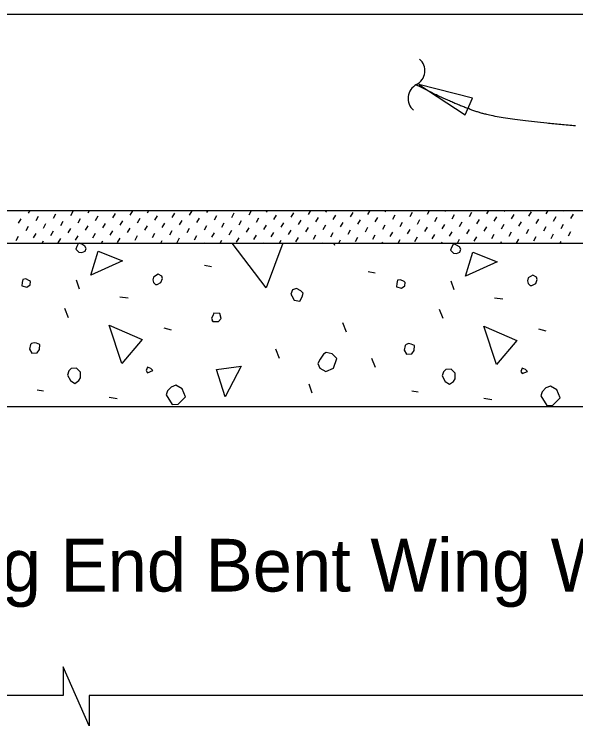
# Model space of a CAD drawing. Extents: x 2.6 to 35.7, y 1.7 to 23.4.
# Drawn here: x 9.781 to 11.926, y 5.942 to 8.663 of the extents above; entities that cross this region are included whole.
import ezdxf

# ---------------------------------------------------------------- set-up
doc = ezdxf.new("R2010")
doc.units = 0
for name, color, linetype in [('Dimension', 7, 'Continuous'), ('Miscellaneous', 7, 'Continuous'), ('TextStructures', 7, 'Continuous'), ('TrafBarrierConc', 7, 'Continuous')]:
    doc.layers.add(name, color=color, linetype=linetype)

msp = doc.modelspace()

# ---------------------------------------------------------------- linework, layer by layer
at = {"layer": 'Dimension'}
msp.add_lwpolyline([(11.327, 8.3948), (11.5032, 8.2783), (11.5318, 8.3428)], close=True, dxfattribs=at)
msp.add_lwpolyline([(12.6311, 6.0586), (10.0672, 6.0586), (10.0672, 5.9424), (9.9678, 6.1674), (9.9678, 6.0586), (8.3596, 6.0586)], dxfattribs=at)
for centre, start, end in [((11.2903, 8.4471), 297.3915, 49.1187), ((11.3452, 8.3413), 117.3915, 229.1187)]:
    msp.add_arc(centre, 0.0596, start, end, dxfattribs=at)
msp.add_open_spline([(11.9256, 8.2363), (11.6526, 8.2589), (11.4737, 8.3129), (11.3181, 8.3921)], degree=2, dxfattribs=at)
at = {"layer": 'Miscellaneous'}
for p, q in [((9.8355, 7.9025), (9.8418, 7.9134)), ((9.9018, 7.9122), (9.9025, 7.9134)), ((9.9301, 7.8839), (9.9398, 7.9007)), ((9.9964, 7.8937), (10.0061, 7.9105)), ((10.0627, 7.9034), (10.0685, 7.9134)), ((10.091, 7.8751), (10.1007, 7.8919)), ((10.129, 7.9131), (10.1291, 7.9134)), ((10.1573, 7.8848), (10.167, 7.9016)), ((10.2236, 7.8946), (10.2333, 7.9113)), ((10.2898, 7.9043), (10.2951, 7.9134)), ((10.3181, 7.876), (10.3279, 7.8928)), ((10.3844, 7.8857), (10.3941, 7.9025)), ((10.4507, 7.8954), (10.4604, 7.9122)), ((10.517, 7.9052), (10.5218, 7.9134)), ((10.5453, 7.8769), (10.555, 7.8937)), ((10.6116, 7.8866), (10.6213, 7.9034)), ((10.6779, 7.8963), (10.6876, 7.9131)), ((10.7442, 7.906), (10.7484, 7.9134)), ((10.7724, 7.8778), (10.7822, 7.8946)), ((10.8387, 7.8875), (10.8485, 7.9043)), ((10.905, 7.8972), (10.9144, 7.9134)), ((10.9713, 7.9069), (10.9751, 7.9134)), ((10.9996, 7.8786), (11.0093, 7.8954)), ((11.0659, 7.8884), (11.0756, 7.9052)), ((11.1322, 7.8981), (11.1411, 7.9134)), ((11.1985, 7.9078), (11.2017, 7.9134)), ((11.2268, 7.8795), (11.2365, 7.8963)), ((11.2931, 7.8893), (11.3028, 7.906)), ((11.3593, 7.899), (11.3677, 7.9134)), ((11.4256, 7.9087), (11.4284, 7.9134)), ((11.4539, 7.8804), (11.4636, 7.8972)), ((11.5202, 7.8901), (11.5299, 7.9069)), ((11.5865, 7.8999), (11.5943, 7.9134)), ((11.6528, 7.9096), (11.655, 7.9134)), ((11.6811, 7.8813), (11.6908, 7.8981)), ((11.7474, 7.891), (11.7571, 7.9078)), ((11.8137, 7.9007), (11.821, 7.9134)), ((11.88, 7.9105), (11.8817, 7.9134)), ((11.9082, 7.8822), (11.918, 7.899)), ((9.7975, 7.8645), (9.8072, 7.8813)), ((9.8638, 7.8742), (9.8735, 7.891)), ((9.9584, 7.8557), (9.9681, 7.8725)), ((10.0247, 7.8654), (10.0344, 7.8822)), ((10.1855, 7.8565), (10.1953, 7.8733)), ((10.2518, 7.8663), (10.2616, 7.8831)), ((10.3464, 7.8477), (10.3561, 7.8645)), ((10.4127, 7.8574), (10.4224, 7.8742)), ((10.479, 7.8672), (10.4887, 7.8839)), ((10.5736, 7.8486), (10.5833, 7.8654)), ((10.6399, 7.8583), (10.6496, 7.8751)), ((10.7062, 7.868), (10.7159, 7.8848)), ((10.8007, 7.8495), (10.8105, 7.8663)), ((10.867, 7.8592), (10.8767, 7.876)), ((10.9333, 7.8689), (10.943, 7.8857)), ((11.0279, 7.8504), (11.0376, 7.8672)), ((11.0942, 7.8601), (11.1039, 7.8769)), ((11.1605, 7.8698), (11.1702, 7.8866)), ((11.255, 7.8512), (11.2648, 7.868)), ((11.3213, 7.861), (11.3311, 7.8778)), ((11.3876, 7.8707), (11.3973, 7.8875)), ((11.4822, 7.8521), (11.4919, 7.8689)), ((11.5485, 7.8619), (11.5582, 7.8786)), ((11.6148, 7.8716), (11.6245, 7.8884)), ((11.7094, 7.853), (11.7191, 7.8698)), ((11.7757, 7.8627), (11.7854, 7.8795)), ((11.8419, 7.8725), (11.8517, 7.8893)), ((9.8258, 7.8362), (9.8355, 7.853)), ((9.8921, 7.8459), (9.9018, 7.8627)), ((9.9867, 7.8274), (9.9964, 7.8442)), ((10.053, 7.8371), (10.0627, 7.8539)), ((10.1193, 7.8468), (10.129, 7.8636)), ((10.2138, 7.8283), (10.2236, 7.8451)), ((10.2801, 7.838), (10.2898, 7.8548)), ((10.441, 7.8291), (10.4507, 7.8459)), ((10.5073, 7.8389), (10.517, 7.8557)), ((10.6019, 7.8203), (10.6116, 7.8371)), ((10.6681, 7.83), (10.6779, 7.8468)), ((10.7344, 7.8398), (10.7442, 7.8565)), ((10.829, 7.8212), (10.8387, 7.838)), ((10.8953, 7.8309), (10.905, 7.8477)), ((10.9616, 7.8406), (10.9713, 7.8574)), ((11.0562, 7.8221), (11.0659, 7.8389)), ((11.1225, 7.8318), (11.1322, 7.8486)), ((11.1888, 7.8415), (11.1985, 7.8583)), ((11.2833, 7.823), (11.2931, 7.8398)), ((11.3496, 7.8327), (11.3593, 7.8495)), ((11.4159, 7.8424), (11.4256, 7.8592)), ((11.5105, 7.8238), (11.5202, 7.8406)), ((11.5768, 7.8336), (11.5865, 7.8504)), ((11.6431, 7.8433), (11.6528, 7.8601)), ((11.7376, 7.8247), (11.7474, 7.8415)), ((11.8039, 7.8345), (11.8137, 7.8512)), ((11.8702, 7.8442), (11.88, 7.861)), ((9.7878, 7.7982), (9.7975, 7.815)), ((9.8541, 7.8079), (9.8638, 7.8247)), ((9.9204, 7.8177), (9.9301, 7.8345)), ((10.015, 7.7991), (10.0247, 7.8159)), ((10.0812, 7.8088), (10.091, 7.8256)), ((10.1475, 7.8185), (10.1573, 7.8353)), ((10.2421, 7.8), (10.2518, 7.8168)), ((10.3084, 7.8097), (10.3181, 7.8265)), ((10.3747, 7.8194), (10.3844, 7.8362)), ((10.4693, 7.8009), (10.479, 7.8177)), ((10.5356, 7.8106), (10.5453, 7.8274)), ((10.6964, 7.8017), (10.7062, 7.8185)), ((10.7627, 7.8115), (10.7724, 7.8283)), ((10.8573, 7.7929), (10.867, 7.8097)), ((10.9236, 7.8026), (10.9333, 7.8194)), ((10.9899, 7.8124), (10.9996, 7.8291)), ((11.0845, 7.7938), (11.0942, 7.8106)), ((11.1507, 7.8035), (11.1605, 7.8203)), ((11.217, 7.8132), (11.2268, 7.83)), ((11.3116, 7.7947), (11.3213, 7.8115)), ((11.3779, 7.8044), (11.3876, 7.8212)), ((11.4442, 7.8141), (11.4539, 7.8309)), ((11.5388, 7.7956), (11.5485, 7.8124)), ((11.6051, 7.8053), (11.6148, 7.8221)), ((11.6714, 7.815), (11.6811, 7.8318)), ((11.7659, 7.7964), (11.7757, 7.8132)), ((11.8322, 7.8062), (11.8419, 7.823)), ((11.8985, 7.8159), (11.9082, 7.8327)), ((9.8874, 7.7884), (9.8921, 7.7964)), ((9.9487, 7.7894), (9.9584, 7.8062)), ((10.1141, 7.7884), (10.1193, 7.7973)), ((10.1758, 7.7903), (10.1855, 7.807)), ((10.2801, 7.7884), (10.2801, 7.7885)), ((10.3407, 7.7884), (10.3464, 7.7982)), ((10.403, 7.7911), (10.4127, 7.8079)), ((10.5067, 7.7884), (10.5073, 7.7894)), ((10.5674, 7.7884), (10.5736, 7.7991)), ((10.6301, 7.792), (10.6399, 7.8088)), ((10.7334, 7.7884), (10.7344, 7.7903)), ((10.794, 7.7884), (10.8007, 7.8)), ((10.96, 7.7884), (10.9616, 7.7911)), ((11.0061, 7.7786), (11.0025, 7.7884)), ((11.0207, 7.7884), (11.0279, 7.8009)), ((11.1867, 7.7884), (11.1888, 7.792)), ((11.2473, 7.7884), (11.255, 7.8017)), ((11.4133, 7.7884), (11.4159, 7.7929)), ((11.474, 7.7884), (11.4822, 7.8026)), ((11.64, 7.7884), (11.6431, 7.7938)), ((11.7006, 7.7884), (11.7094, 7.8035)), ((11.8666, 7.7884), (11.8702, 7.7947)), ((10.5076, 7.7043), (10.5341, 7.699)), ((11.1334, 7.6796), (11.1599, 7.6743)), ((10.0303, 7.6124), (10.0179, 7.646)), ((11.4622, 7.6089), (11.4498, 7.6425)), ((10.1841, 7.5824), (10.2159, 7.5788)), ((11.616, 7.5788), (11.6478, 7.5753)), ((9.9879, 7.5028), (9.9737, 7.5382)), ((11.4198, 7.4993), (11.4056, 7.5346)), ((11.0503, 7.448), (11.0362, 7.4834)), ((10.352, 7.4639), (10.3803, 7.4568)), ((11.7839, 7.4604), (11.8122, 7.4533)), ((10.794, 7.3472), (10.7798, 7.3826)), ((11.1617, 7.3119), (11.1475, 7.3472)), ((10.9195, 7.2147), (10.9071, 7.2483)), ((9.8677, 7.227), (9.8924, 7.2235)), ((11.2996, 7.2235), (11.3243, 7.22)), ((10.1435, 7.1988), (10.1735, 7.1935)), ((11.5753, 7.1952), (11.6054, 7.1899))]:
    msp.add_line(p, q, dxfattribs=at)
for points in [[(10.0264, 7.7884), (10.0197, 7.775), (10.0162, 7.7644), (10.0268, 7.7538)], [(10.0268, 7.7538), (10.0392, 7.7521), (10.0515, 7.7574), (10.0551, 7.768), (10.0498, 7.7768), (10.0392, 7.7839), (10.0286, 7.7884)], [(10.7427, 7.6177), (10.613, 7.7884)], [(10.8065, 7.7884), (10.7427, 7.6177)], [(11.4587, 7.7503), (11.471, 7.7485), (11.4834, 7.7538), (11.487, 7.7644), (11.4817, 7.7733), (11.471, 7.7803), (11.4587, 7.7857), (11.4516, 7.7715), (11.4481, 7.7609), (11.4587, 7.7503)], [(10.0727, 7.6654), (10.101, 7.7574), (10.1947, 7.7202), (10.0727, 7.6654)], [(11.5046, 7.6619), (11.5329, 7.7538), (11.6266, 7.7167), (11.5046, 7.6619)], [(9.8093, 7.6248), (9.8288, 7.6195), (9.8412, 7.6283), (9.8429, 7.6407), (9.8394, 7.6442), (9.8253, 7.6513), (9.8129, 7.6495), (9.8111, 7.6372), (9.8093, 7.6248)], [(10.3202, 7.6301), (10.3273, 7.6301), (10.3414, 7.6372), (10.3467, 7.6531), (10.345, 7.6619), (10.3308, 7.669), (10.3132, 7.6584), (10.3096, 7.6478), (10.3132, 7.6372), (10.3202, 7.6301)], [(11.2412, 7.6213), (11.2607, 7.6159), (11.2731, 7.6248), (11.2748, 7.6372), (11.2713, 7.6407), (11.2571, 7.6478), (11.2448, 7.646), (11.243, 7.6336), (11.2412, 7.6213)], [(11.7521, 7.6266), (11.7592, 7.6266), (11.7733, 7.6336), (11.7786, 7.6495), (11.7769, 7.6584), (11.7627, 7.6654), (11.745, 7.6548), (11.7415, 7.6442), (11.745, 7.6336), (11.7521, 7.6266)], [(10.8417, 7.5859), (10.8506, 7.57), (10.8718, 7.5664), (10.8806, 7.5824), (10.8841, 7.5965), (10.8753, 7.6053), (10.8594, 7.6142), (10.8435, 7.6089), (10.8382, 7.593), (10.8417, 7.5859)], [(10.5394, 7.4887), (10.5606, 7.4887), (10.5713, 7.4993), (10.5659, 7.5187), (10.543, 7.5205), (10.5394, 7.5099), (10.5341, 7.501), (10.5394, 7.4887), (10.5359, 7.4922)], [(10.1912, 7.3278), (10.1435, 7.4745), (10.269, 7.4197), (10.1912, 7.3278)], [(11.6231, 7.3243), (11.5753, 7.471), (11.7009, 7.4162), (11.6231, 7.3243)], [(9.8394, 7.3826), (9.8482, 7.3667), (9.8677, 7.3685), (9.8765, 7.3808), (9.8783, 7.4003), (9.8659, 7.4056), (9.8571, 7.4074), (9.8465, 7.4038), (9.8429, 7.4003), (9.8394, 7.3826)], [(11.2713, 7.3791), (11.2801, 7.3632), (11.2996, 7.3649), (11.3084, 7.3773), (11.3102, 7.3967), (11.2978, 7.402), (11.289, 7.4038), (11.2784, 7.4003), (11.2748, 7.3967), (11.2713, 7.3791)], [(10.9478, 7.3101), (10.9708, 7.2977), (11.0008, 7.3101), (11.0132, 7.3472), (10.9955, 7.3649), (10.9725, 7.3702), (10.9619, 7.3632), (10.9496, 7.3437), (10.9407, 7.3278), (10.9478, 7.3101)], [(9.9844, 7.2836), (9.995, 7.2624), (10.0126, 7.2518), (10.0268, 7.2624), (10.0338, 7.273), (10.0338, 7.2942), (10.0179, 7.3101), (9.9985, 7.3084), (9.9897, 7.2995), (9.9844, 7.2836)], [(10.2902, 7.2924), (10.3096, 7.3013), (10.3026, 7.3084), (10.2902, 7.3137), (10.2849, 7.3013), (10.2902, 7.2924)], [(10.5872, 7.2005), (10.5536, 7.3048), (10.6473, 7.3172), (10.5872, 7.2005)], [(11.4162, 7.2801), (11.4269, 7.2589), (11.4445, 7.2483), (11.4587, 7.2589), (11.4657, 7.2695), (11.4657, 7.2907), (11.4498, 7.3066), (11.4304, 7.3048), (11.4215, 7.296), (11.4162, 7.2801)], [(11.7221, 7.2889), (11.7415, 7.2977), (11.7344, 7.3048), (11.7221, 7.3101), (11.7168, 7.2977), (11.7221, 7.2889)], [(10.3609, 7.2076), (10.3839, 7.1705), (10.4068, 7.1722), (10.4157, 7.1811), (10.4351, 7.2005), (10.4228, 7.2306), (10.398, 7.2447), (10.3803, 7.2376), (10.3662, 7.2235), (10.3609, 7.2076)], [(11.7928, 7.2041), (11.8158, 7.1669), (11.8387, 7.1687), (11.8476, 7.1775), (11.867, 7.197), (11.8546, 7.227), (11.8299, 7.2412), (11.8122, 7.2341), (11.7981, 7.22), (11.7928, 7.2041)]]:
    msp.add_lwpolyline(points, dxfattribs=at)
at = {"layer": 'TrafBarrierConc'}
for p, q in [((8.4846, 8.6634), (17.4572, 8.6634)), ((8.4846, 7.9134), (17.9962, 7.9134)), ((8.4846, 7.7884), (17.9962, 7.7884)), ((8.4846, 7.1633), (17.9962, 7.1633))]:
    msp.add_line(p, q, dxfattribs=at)

# ---------------------------------------------------------------- texts
at = {"layer": 'TextStructures'}
msp.add_text('Existing End Bent Wing Wall', height=0.2016, dxfattribs=at).set_placement((8.9388, 6.4557))

doc.saveas('drawing.dxf')
